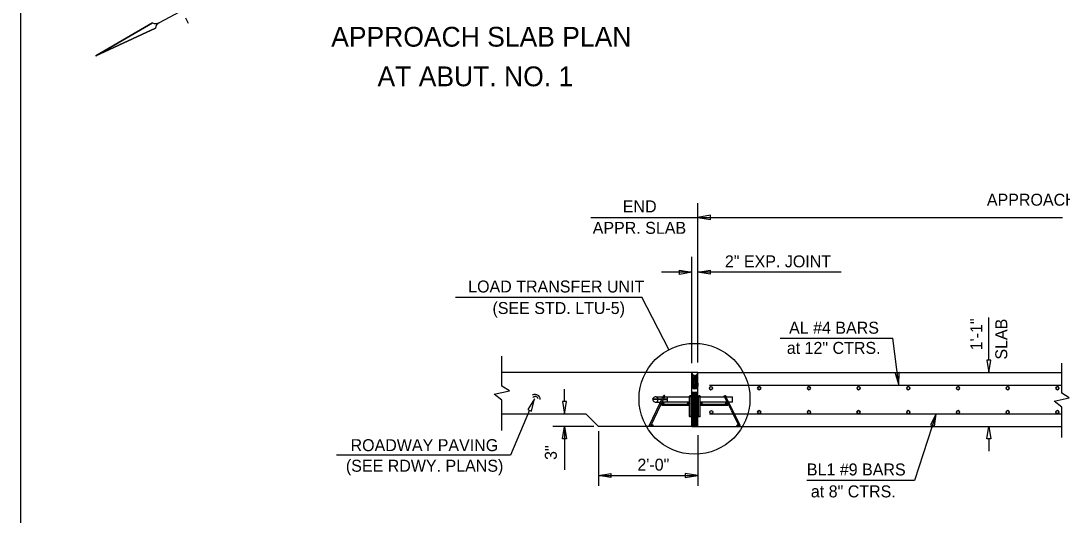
# Model space of a CAD drawing. Extents: x 570 to 2152770, y -27 to 139926.
# Drawn here: x 2151056.2 to 2151140, y 138814.7 to 138854.5 of the extents above; entities that cross this region are included whole.
import ezdxf

# ---------------------------------------------------------------- set-up
doc = ezdxf.new("R2010")
doc.units = 0
for name, color, linetype in [('4', 7, 'Continuous'), ('5', 7, 'Continuous'), ('6', 7, 'Continuous'), ('Default', 7, 'Continuous'), ('HATCH', 7, 'Continuous'), ('PR_Dimensions', 7, 'Continuous'), ('PR_Reinforcing', 7, 'Continuous'), ('SHT_Sheet_Border', 7, 'Continuous'), ('T', 7, 'Continuous'), ('T-Title', 7, 'Continuous')]:
    doc.layers.add(name, color=color, linetype=linetype)

# ---------------------------------------------------------------- blocks, each defined once
blk = doc.blocks.new('ARROWHD_7')
at = {"layer": 'Default'}
blk.add_lwpolyline([(0.0261, -0.0045), (0.0261, 0.0043), (-0.0004, -0.0001)], close=True, dxfattribs=at)

msp = doc.modelspace()

# ---------------------------------------------------------------- linework, layer by layer
at = {"layer": '4'}
for p, q in [((2151110.155, 138826.154), (2151094.883, 138826.154)), ((2151110.155, 138821.821), (2151110.155, 138826.154)), ((2151101.655, 138822.821), (2151094.883, 138822.821)), ((2151102.655, 138821.821), (2151101.655, 138822.821)), ((2151110.155, 138821.821), (2151102.655, 138821.821))]:
    msp.add_line(p, q, dxfattribs=at)
at = {"layer": '5'}
for p, q in [((2151110.655, 138826.154), (2151139.951, 138826.154)), ((2151110.655, 138821.821), (2151110.655, 138826.154)), ((2151110.655, 138821.821), (2151139.951, 138821.821))]:
    msp.add_line(p, q, dxfattribs=at)
at = {"layer": '6'}
for p, q in [((2151106.728, 138821.882), (2151107.879, 138824.276)), ((2151109.975, 138822.622), (2151109.975, 138824.255)), ((2151110.107, 138822.616), (2151110.107, 138824.255)), ((2151110.17, 138824.558), (2151110.17, 138821.821)), ((2151110.703, 138822.616), (2151110.703, 138824.255)), ((2151110.835, 138822.622), (2151110.835, 138824.255)), ((2151114.076, 138821.874), (2151112.881, 138824.29)), ((2151106.841, 138821.821), (2151107.991, 138824.229)), ((2151107.742, 138823.991), (2151106.993, 138823.991)), ((2151107.75, 138824.008), (2151106.996, 138824.008)), ((2151107.288, 138824.209), (2151107.847, 138824.209)), ((2151107.297, 138823.768), (2151107.634, 138823.768)), ((2151107.424, 138823.768), (2151107.424, 138824.209)), ((2151107.607, 138823.71), (2151107.72, 138823.658)), ((2151107.737, 138823.612), (2151109.975, 138823.612)), ((2151107.737, 138823.543), (2151107.737, 138823.612)), ((2151107.737, 138823.543), (2151109.975, 138823.543)), ((2151107.756, 138823.671), (2151107.844, 138823.758)), ((2151107.77, 138823.732), (2151107.782, 138823.743)), ((2151107.772, 138823.639), (2151107.875, 138823.743)), ((2151109.975, 138823.771), (2151107.775, 138823.771)), ((2151107.799, 138823.619), (2151107.896, 138823.716)), ((2151107.841, 138823.614), (2151107.901, 138823.674)), ((2151108.217, 138823.978), (2151107.875, 138823.978)), ((2151108.217, 138824.015), (2151107.892, 138824.015)), ((2151107.979, 138824.205), (2151109.975, 138824.205)), ((2151108.217, 138824.015), (2151108.217, 138824.199)), ((2151108.217, 138823.771), (2151108.217, 138823.978)), ((2151109.87, 138823.617), (2151109.816, 138823.67)), ((2151109.916, 138823.617), (2151109.817, 138823.717)), ((2151109.946, 138823.634), (2151109.834, 138823.746)), ((2151109.965, 138823.662), (2151109.862, 138823.766)), ((2151109.971, 138823.704), (2151109.904, 138823.771)), ((2151110.155, 138824.205), (2151110.655, 138824.205)), ((2151110.655, 138823.771), (2151110.155, 138823.771)), ((2151110.835, 138824.205), (2151112.79, 138824.205)), ((2151113.006, 138823.771), (2151110.835, 138823.771)), ((2151110.835, 138823.612), (2151112.9, 138823.612)), ((2151110.835, 138823.543), (2151113.05, 138823.543)), ((2151110.84, 138823.704), (2151110.907, 138823.771)), ((2151110.845, 138823.662), (2151110.949, 138823.766)), ((2151110.864, 138823.634), (2151110.976, 138823.746)), ((2151110.894, 138823.617), (2151110.994, 138823.717)), ((2151110.941, 138823.617), (2151110.994, 138823.67)), ((2151112.778, 138824.229), (2151113.317, 138823.148)), ((2151112.872, 138823.692), (2151112.952, 138823.772)), ((2151112.882, 138823.655), (2151112.99, 138823.762)), ((2151112.904, 138823.629), (2151113.015, 138823.74)), ((2151112.918, 138823.612), (2151113.05, 138823.612)), ((2151112.923, 138824.205), (2151113.426, 138824.205)), ((2151112.936, 138823.615), (2151113.029, 138823.708)), ((2151112.994, 138823.626), (2151113.019, 138823.65)), ((2151113.05, 138823.543), (2151113.05, 138823.612)), ((2151113.426, 138823.771), (2151113.138, 138823.771)), ((2151113.426, 138823.771), (2151113.426, 138824.205)), ((2151113.327, 138823.128), (2151113.978, 138821.821)), ((2151106.841, 138821.821), (2151106.728, 138821.882)), ((2151106.953, 138821.826), (2151106.898, 138821.881)), ((2151106.995, 138821.831), (2151106.903, 138821.923)), ((2151107.021, 138821.852), (2151106.924, 138821.949)), ((2151107.035, 138821.886), (2151106.958, 138821.963)), ((2151113.785, 138821.886), (2151113.861, 138821.963)), ((2151113.798, 138821.852), (2151113.895, 138821.949)), ((2151113.824, 138821.831), (2151113.916, 138821.923)), ((2151113.866, 138821.826), (2151113.921, 138821.881)), ((2151113.978, 138821.821), (2151114.076, 138821.874))]:
    msp.add_line(p, q, dxfattribs=at)
msp.add_lwpolyline([(2151126.854, 138826.167), (2151126.523, 138826.126), (2151126.813, 138825.154)], close=True, dxfattribs=at)
for centre, radius in [((2151110.041, 138824.255), 0.0661), ((2151110.769, 138824.255), 0.0661), ((2151112.829, 138824.263), 0.0579), ((2151107.357, 138824.183), 0.026), ((2151107.36, 138823.793), 0.026), ((2151107.828, 138823.686), 0.0737), ((2151109.892, 138823.693), 0.0795), ((2151110.918, 138823.693), 0.0795), ((2151112.952, 138823.693), 0.0795), ((2151106.966, 138821.894), 0.0694), ((2151113.853, 138821.894), 0.0694)]:
    msp.add_circle(centre, radius, dxfattribs=at)
for centre, start, end in [((2151107.932, 138824.249), 175.26567, 325.2905), ((2151107.933, 138824.248), 342.58025, 154.17462)]:
    msp.add_arc(centre, 0.0607, start, end, dxfattribs=at)
for centre, major_axis, ratio, start_param, end_param in [((2151107.285, 138824.081), (0.116, -0.293), 0.968884, 4.638831, 5.955744), ((2151107.285, 138823.909), (-0.284, 0.112), 0.981158, 5.03983, 6.32816), ((2151110.044, 138822.623), (0.0633, -0.0007), 0.370294, 0, 6.283175), ((2151110.766, 138822.623), (-0.0633, -0.0007), 0.370294, 0, 6.283175)]:
    msp.add_ellipse(centre, major_axis=major_axis, ratio=ratio, start_param=start_param, end_param=end_param, dxfattribs=at)
at = {"layer": 'HATCH'}
for p, q in [((2151110.655, 138826.154), (2151110.155, 138826.154)), ((2151110.178, 138826.096), (2151110.164, 138826.11)), ((2151110.164, 138826.082), (2151110.178, 138826.096)), ((2151110.165, 138825.403), (2151110.165, 138826.146)), ((2151110.165, 138825.933), (2151110.236, 138826.005)), ((2151110.165, 138825.488), (2151110.646, 138825.969)), ((2151110.646, 138825.479), (2151110.165, 138825.961)), ((2151110.165, 138825.785), (2151110.33, 138825.95)), ((2151110.165, 138825.636), (2151110.477, 138825.949)), ((2151110.646, 138825.628), (2151110.322, 138825.953)), ((2151110.646, 138825.777), (2151110.475, 138825.948)), ((2151110.646, 138825.925), (2151110.569, 138826.002)), ((2151110.646, 138826.074), (2151110.63, 138826.09)), ((2151110.637, 138826.108), (2151110.646, 138826.118)), ((2151110.646, 138825.394), (2151110.646, 138826.155)), ((2151110.324, 138825.653), (2151110.165, 138825.812)), ((2151110.242, 138825.586), (2151110.165, 138825.664)), ((2151110.471, 138825.645), (2151110.646, 138825.821)), ((2151110.554, 138825.58), (2151110.646, 138825.672)), ((2151110.17, 138824.265), (2151110.463, 138824.558)), ((2151110.17, 138824.314), (2151110.414, 138824.558)), ((2151110.17, 138824.364), (2151110.364, 138824.558)), ((2151110.17, 138824.413), (2151110.315, 138824.558)), ((2151110.17, 138824.463), (2151110.265, 138824.558)), ((2151110.17, 138824.512), (2151110.216, 138824.558)), ((2151110.64, 138824.558), (2151110.17, 138824.558)), ((2151110.17, 138824.116), (2151110.612, 138824.558)), ((2151110.17, 138824.166), (2151110.562, 138824.558)), ((2151110.17, 138824.215), (2151110.513, 138824.558)), ((2151110.17, 138824.067), (2151110.64, 138824.537)), ((2151110.17, 138824.017), (2151110.64, 138824.487)), ((2151110.17, 138823.967), (2151110.64, 138824.438)), ((2151110.17, 138823.918), (2151110.64, 138824.388)), ((2151110.17, 138823.868), (2151110.64, 138824.339)), ((2151110.17, 138823.819), (2151110.64, 138824.289)), ((2151110.64, 138821.821), (2151110.64, 138824.558)), ((2151110.17, 138823.769), (2151110.64, 138824.24)), ((2151110.17, 138823.72), (2151110.64, 138824.19)), ((2151110.17, 138823.67), (2151110.64, 138824.141)), ((2151110.17, 138823.621), (2151110.64, 138824.091)), ((2151110.17, 138823.571), (2151110.64, 138824.042)), ((2151110.17, 138823.522), (2151110.64, 138823.992)), ((2151110.17, 138823.472), (2151110.64, 138823.942)), ((2151110.17, 138823.422), (2151110.64, 138823.893)), ((2151110.17, 138823.373), (2151110.64, 138823.843)), ((2151110.17, 138823.323), (2151110.64, 138823.794)), ((2151110.17, 138823.274), (2151110.64, 138823.744)), ((2151110.17, 138823.224), (2151110.64, 138823.695)), ((2151110.17, 138823.175), (2151110.64, 138823.645)), ((2151110.17, 138823.125), (2151110.64, 138823.596)), ((2151110.17, 138823.076), (2151110.64, 138823.546)), ((2151110.17, 138823.026), (2151110.64, 138823.497)), ((2151110.17, 138822.977), (2151110.64, 138823.447)), ((2151110.17, 138822.927), (2151110.64, 138823.397)), ((2151110.17, 138822.877), (2151110.64, 138823.348)), ((2151110.17, 138822.828), (2151110.64, 138823.298)), ((2151110.17, 138822.778), (2151110.64, 138823.249)), ((2151110.17, 138822.729), (2151110.64, 138823.199)), ((2151110.17, 138822.679), (2151110.64, 138823.15)), ((2151110.17, 138822.63), (2151110.64, 138823.1)), ((2151110.17, 138822.58), (2151110.64, 138823.051)), ((2151110.17, 138822.531), (2151110.64, 138823.001)), ((2151110.17, 138822.481), (2151110.64, 138822.952)), ((2151110.17, 138822.432), (2151110.64, 138822.902)), ((2151110.17, 138822.382), (2151110.64, 138822.852)), ((2151110.17, 138822.332), (2151110.64, 138822.803)), ((2151110.17, 138822.283), (2151110.64, 138822.753)), ((2151110.17, 138822.233), (2151110.64, 138822.704)), ((2151110.17, 138822.184), (2151110.64, 138822.654)), ((2151110.17, 138822.134), (2151110.64, 138822.604)), ((2151110.17, 138822.084), (2151110.64, 138822.555)), ((2151110.17, 138822.035), (2151110.64, 138822.505)), ((2151110.17, 138821.985), (2151110.64, 138822.456)), ((2151110.17, 138821.936), (2151110.64, 138822.406)), ((2151110.17, 138821.886), (2151110.64, 138822.357)), ((2151110.17, 138821.837), (2151110.64, 138822.307)), ((2151110.17, 138821.821), (2151110.64, 138821.821)), ((2151110.204, 138821.821), (2151110.64, 138822.257)), ((2151110.254, 138821.821), (2151110.64, 138822.208)), ((2151110.303, 138821.821), (2151110.64, 138822.158)), ((2151110.353, 138821.821), (2151110.64, 138822.109)), ((2151110.403, 138821.821), (2151110.64, 138822.059)), ((2151110.452, 138821.821), (2151110.64, 138822.01)), ((2151110.502, 138821.821), (2151110.64, 138821.96)), ((2151110.551, 138821.821), (2151110.64, 138821.91)), ((2151110.601, 138821.821), (2151110.64, 138821.861))]:
    msp.add_line(p, q, dxfattribs=at)
msp.add_arc((2151110.405, 138826.18), 0.243, 188.11819, 354.01473, dxfattribs=at)
for centre, major_axis, ratio in [((2151110.402, 138825.238), (-0.006, 0.417), 0.604578), ((2151110.208, 138825.209), (0, -0.0579), 0.713524), ((2151110.225, 138825.36), (0, -0.0579), 0.713524), ((2151110.237, 138825.076), (0, -0.0579), 0.713524), ((2151110.292, 138825.493), (0, -0.0579), 0.713524), ((2151110.304, 138825.235), (0, -0.0579), 0.713524), ((2151110.341, 138825.09), (0, -0.0579), 0.713524), ((2151110.353, 138825.377), (0, -0.0579), 0.713524), ((2151110.399, 138825.557), (0, -0.0579), 0.713524), ((2151110.405, 138825.238), (0, -0.0579), 0.713524), ((2151110.44, 138825.093), (0, -0.0579), 0.713524), ((2151110.454, 138825.374), (0, -0.0579), 0.713524), ((2151110.5, 138825.241), (0, -0.0579), 0.713524), ((2151110.506, 138825.496), (0, -0.0579), 0.713524), ((2151110.567, 138825.099), (0, -0.0579), 0.713524), ((2151110.578, 138825.365), (0, -0.0579), 0.713524), ((2151110.596, 138825.232), (0, -0.0579), 0.713524), ((2151110.312, 138824.96), (0, -0.0579), 0.713524), ((2151110.408, 138824.911), (0, -0.0579), 0.713524), ((2151110.497, 138824.977), (0, -0.0579), 0.713524)]:
    msp.add_ellipse(centre, major_axis=major_axis, ratio=ratio, start_param=0, end_param=6.283175, dxfattribs=at)
at = {"layer": 'PR_Dimensions'}
for p, q in [((2151068.953, 138855.192), (2151067.293, 138854.329)), ((2151069.411, 138854.728), (2151069.632, 138854.302)), ((2151062.186, 138851.671), (2151066.767, 138854.326)), ((2151066.767, 138854.326), (2151062.186, 138851.671)), ((2151066.989, 138853.899), (2151062.186, 138851.671)), ((2151062.186, 138851.671), (2151066.989, 138853.899)), ((2151110.655, 138826.96), (2151110.655, 138839.797)), ((2151102.046, 138838.654), (2151110.655, 138838.654)), ((2151110.655, 138838.654), (2151139.987, 138838.654)), ((2151110.155, 138826.914), (2151110.155, 138835.469)), ((2151110.155, 138834.238), (2151107.728, 138834.238)), ((2151122.169, 138834.238), (2151110.655, 138834.238)), ((2151091.151, 138832.238), (2151106.127, 138832.238)), ((2151108.321, 138828.012), (2151106.127, 138832.238)), ((2151134.061, 138827.154), (2151134.061, 138830.582)), ((2151117.262, 138828.934), (2151126.338, 138828.934)), ((2151126.813, 138825.154), (2151126.338, 138828.934)), ((2151094.883, 138825.063), (2151094.883, 138827.472)), ((2151139.951, 138824.5), (2151139.951, 138826.91)), ((2151099.913, 138823.821), (2151099.913, 138824.821)), ((2151094.883, 138821.496), (2151094.883, 138823.947)), ((2151097.105, 138823.122), (2151095.56, 138819.5)), ((2151129.833, 138822.832), (2151128.079, 138817.467)), ((2151139.951, 138820.934), (2151139.951, 138823.385)), ((2151102.265, 138821.821), (2151098.966, 138821.821)), ((2151099.913, 138821.821), (2151099.913, 138818.342)), ((2151102.655, 138821.434), (2151102.655, 138817.042)), ((2151110.655, 138821.132), (2151110.655, 138817.042)), ((2151134.061, 138820.821), (2151134.061, 138819.821)), ((2151095.56, 138819.5), (2151081.57, 138819.5)), ((2151102.655, 138817.871), (2151110.625, 138817.871)), ((2151128.079, 138817.467), (2151119.423, 138817.467))]:
    msp.add_line(p, q, dxfattribs=at)
for points in [[(2151111.655, 138838.488), (2151111.655, 138838.821), (2151110.655, 138838.654)], [(2151134.228, 138827.154), (2151133.894, 138827.154), (2151134.061, 138826.154)], [(2151096.952, 138823.189), (2151097.258, 138823.055), (2151097.506, 138824.038)], [(2151100.08, 138823.821), (2151099.746, 138823.821), (2151099.913, 138822.821)], [(2151100.08, 138820.821), (2151099.746, 138820.821), (2151099.913, 138821.821)], [(2151134.228, 138820.821), (2151133.894, 138820.821), (2151134.061, 138821.821)]]:
    msp.add_lwpolyline(points, close=True, dxfattribs=at)
for points in [[(2151094.883, 138823.947), (2151094.248, 138824.421), (2151095.477, 138824.691), (2151094.883, 138825.063)], [(2151139.951, 138823.385), (2151139.316, 138823.859), (2151140.545, 138824.128), (2151139.951, 138824.5)]]:
    msp.add_lwpolyline(points, dxfattribs=at)
msp.add_circle((2151110.378, 138824.048), 4.465, dxfattribs=at)
for centre, radius, start, end in [((2151067.027, 138854.839), 0.576, 243.11332, 297.49348), ((2151067.027, 138854.839), 0.576, 243.11332, 297.49348), ((2151067.559, 138853.818), 0.576, 117.49348, 171.87364), ((2151067.559, 138853.818), 0.576, 117.49348, 171.87364), ((2151097.541, 138823.847), 0.542, 99.43484, 114.84323), ((2151097.528, 138823.923), 0.465, 82.12555, 99.43484), ((2151097.507, 138823.771), 0.618, 74.23868, 82.12555), ((2151097.52, 138823.817), 0.57, 65.89652, 74.23868), ((2151097.622, 138824.044), 0.322, 28.11751, 65.89652), ((2151097.571, 138823.854), 0.375, 109.234, 124.64238), ((2151097.545, 138823.927), 0.298, 91.9247, 109.234), ((2151097.551, 138823.773), 0.451, 84.03784, 91.9247), ((2151097.556, 138823.821), 0.404, 75.69568, 84.03784), ((2151097.617, 138824.062), 0.155, 37.91667, 75.69568), ((2151097.548, 138824.008), 0.243, 7.93572, 37.91667), ((2151097.544, 138824.003), 0.41, 358.13657, 28.11751)]:
    msp.add_arc(centre, radius, start, end, dxfattribs=at)
at = {"layer": 'PR_Reinforcing'}
for p, q in [((2151111.581, 138825.154), (2151139.951, 138825.154)), ((2151111.581, 138822.832), (2151139.951, 138822.832))]:
    msp.add_line(p, q, dxfattribs=at)
for centre in [(2151111.7, 138824.903), (2151115.586, 138824.9), (2151119.584, 138824.91), (2151123.586, 138824.909), (2151127.586, 138824.903), (2151131.588, 138824.908), (2151135.589, 138824.908), (2151139.588, 138824.909), (2151111.738, 138822.977), (2151115.584, 138822.973), (2151119.589, 138822.973), (2151123.58, 138822.971), (2151127.584, 138822.974), (2151131.59, 138822.976), (2151135.586, 138822.972), (2151139.586, 138822.978)]:
    msp.add_circle(centre, 0.125, dxfattribs=at)
for centre, start, end in [((2151111.703, 138824.9), 0, 180), ((2151111.703, 138824.9), 180, 0), ((2151115.586, 138824.909), 0, 180), ((2151115.586, 138824.909), 180, 0), ((2151119.586, 138824.909), 0, 180), ((2151119.586, 138824.909), 180, 0), ((2151123.586, 138824.909), 0, 180), ((2151123.586, 138824.909), 180, 0), ((2151127.586, 138824.909), 0, 180), ((2151127.586, 138824.909), 180, 0), ((2151131.586, 138824.909), 0, 180), ((2151131.586, 138824.909), 180, 0), ((2151135.586, 138824.909), 0, 180), ((2151135.586, 138824.909), 180, 0), ((2151139.586, 138824.909), 0, 180), ((2151139.586, 138824.909), 180, 0), ((2151115.586, 138822.975), 0, 180), ((2151115.586, 138822.975), 180, 0), ((2151119.586, 138822.975), 0, 180), ((2151119.586, 138822.975), 180, 0), ((2151123.586, 138822.975), 0, 180), ((2151123.586, 138822.975), 180, 0), ((2151127.586, 138822.975), 0, 180), ((2151127.586, 138822.975), 180, 0), ((2151131.586, 138822.975), 0, 180), ((2151131.586, 138822.975), 180, 0), ((2151135.586, 138822.975), 0, 180), ((2151135.586, 138822.975), 180, 0), ((2151139.586, 138822.975), 0, 180), ((2151139.586, 138822.975), 180, 0)]:
    msp.add_arc(centre, 0.125, start, end, dxfattribs=at)
at = {"layer": 'SHT_Sheet_Border'}
msp.add_lwpolyline([(2151308.159, 138748.654), (2151056.159, 138748.654), (2151056.159, 138916.654), (2151308.159, 138916.654)], close=True, dxfattribs=at)

# ---------------------------------------------------------------- block references
at = {"layer": 'PR_Dimensions', "xscale": 37.7952}
for p, yscale, rotation in [((2151110.155, 138834.238), -37.7952, -180), ((2151129.833, 138822.832), 37.7952, -108.11122555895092), ((2151110.625, 138817.871), 37.7952, -180)]:
    msp.add_blockref('ARROWHD_7', p, dxfattribs=dict(at, yscale=yscale, rotation=rotation))
at = {"layer": 'PR_Dimensions', "xscale": 37.7952, "yscale": -37.7952}
for p in [(2151110.655, 138834.238), (2151102.655, 138817.871)]:
    msp.add_blockref('ARROWHD_7', p, dxfattribs=at)

# ---------------------------------------------------------------- texts
at = {"layer": 'T'}
for s, height, p in [('APPROACH SLAB', 0.96354, (2151133.909, 138839.596)), ('END', 0.9635, (2151104.608, 138839.059)), ('APPR. SLAB', 0.9635, (2151102.186, 138837.331)), ('2" EXP. JOINT', 0.96354, (2151112.823, 138834.632)), ('LOAD TRANSFER UNIT', 0.96354, (2151092.163, 138832.609)), ('(SEE STD. LTU-5)', 0.96354, (2151094.117, 138830.876)), ('AL #4 BARS', 0.9635, (2151117.989, 138829.29)), ('at 12" CTRS.', 0.96354, (2151117.806, 138827.667)), ('ROADWAY PAVING', 0.96354, (2151082.696, 138819.834)), ('2\'-0"', 0.9635, (2151105.782, 138818.266)), ('(SEE RDWY. PLANS)', 0.96354, (2151082.321, 138818.177)), ('BL1 #9 BARS', 0.96354, (2151119.42, 138817.878)), ('at 8" CTRS.', 0.96354, (2151119.744, 138816.111))]:
    msp.add_text(s, height=height, dxfattribs=at).set_placement(p)
for s, p in [('1\'-1"', (2151133.537, 138827.954)), ('SLAB', (2151135.549, 138827.205)), ('3"', (2151099.297, 138819.127))]:
    msp.add_text(s, height=0.9635, rotation=90, dxfattribs=at).set_placement(p)
at = {"layer": 'T-Title'}
for s, p in [('APPROACH SLAB PLAN', (2151081.139, 138852.402)), ('AT ABUT. NO. 1', (2151084.867, 138849.214))]:
    msp.add_text(s, height=1.59375, dxfattribs=at).set_placement(p)

doc.saveas('drawing.dxf')
